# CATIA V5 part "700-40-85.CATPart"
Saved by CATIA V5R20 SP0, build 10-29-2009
Part number: 700-40-85
Revision: ANY
Definition: UNKNOWN
Nomenclature: 700-40-85
Source: Unknown
Bounding box of the stored display mesh (mm): x -20 to 20, y 0 to 85, z -20 to 20
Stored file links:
  C:\Users\Utente\Desktop\IO LAVORO\3D X SITO CF\X SITO\700\700-40-85.CATPart
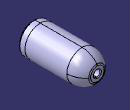
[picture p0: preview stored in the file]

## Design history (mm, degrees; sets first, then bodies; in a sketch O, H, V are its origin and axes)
Body1 "Smusso1" (main body)
  Solid1: solid without history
